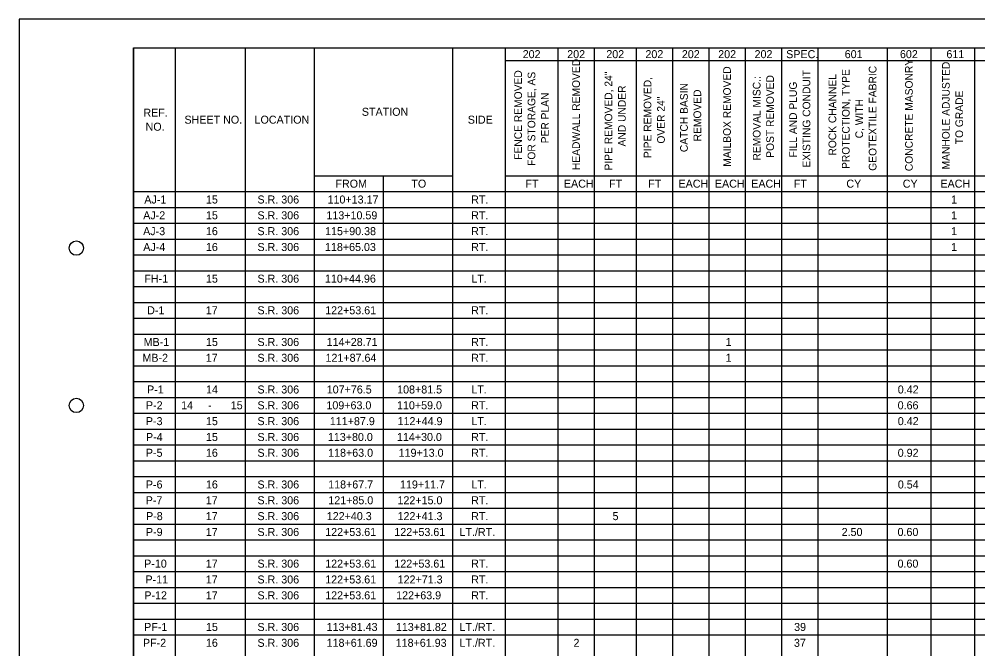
# Model space of a CAD drawing. Extents: x -16 to 102, y -13 to 9.
# Drawn here: x -16.37 to 0.4, y -1.91 to 9.09 of the extents above; entities that cross this region are included whole.
import ezdxf

# ---------------------------------------------------------------- set-up
doc = ezdxf.new("R2010")
doc.units = 0
for name, color, linetype in [('PV_P_EOP', 7, 'Continuous'), ('SH_Border', 7, 'Continuous'), ('SH_Cut_Line', 7, 'Continuous'), ('SH_Text', 7, 'Continuous'), ('TX_P_1', 7, 'Continuous')]:
    doc.layers.add(name, color=color, linetype=linetype)

msp = doc.modelspace()

# ---------------------------------------------------------------- linework, layer by layer
at = {"layer": 'SH_Border'}
msp.add_lwpolyline([(-14.371, 8.593), (17.129, 8.593), (17.129, -12.407), (-14.371, -12.407)], close=True, dxfattribs=at)
for centre in [(-15.371, 5.093), (-15.371, 2.343)]:
    msp.add_circle(centre, 0.125, dxfattribs=at)
at = {"layer": 'SH_Cut_Line'}
msp.add_lwpolyline([(-16.371, -12.907), (17.629, -12.907), (17.629, 9.093), (-16.371, 9.093)], close=True, dxfattribs=at)
at = {"layer": 'SH_Text'}
for p, q in [((-14.371, 8.593), (-12.42, 8.593)), ((-14.371, 8.593), (-14.371, -11.35)), ((-13.64, 8.593), (-13.64, -11.35)), ((-12.42, 8.593), (-10.002, 8.593)), ((-12.42, 8.593), (-12.42, -11.35)), ((-11.211, 8.593), (-11.211, -11.35)), ((-10.002, 8.593), (1.736, 8.593)), ((-8.793, 8.593), (-8.793, -11.35)), ((-7.871, 8.593), (-7.871, -11.881)), ((-6.948, 8.593), (-6.948, -11.881)), ((-6.312, 8.593), (-6.312, -11.881)), ((-5.58, 8.593), (-5.58, -11.881)), ((-4.944, 8.593), (-4.944, -11.881)), ((-4.308, 8.593), (-4.308, -11.881)), ((-3.672, 8.593), (-3.672, -11.881)), ((-3.035, 8.593), (-3.035, -11.881)), ((-2.399, 8.593), (-2.399, -11.881)), ((-1.19, 8.593), (-1.19, -11.881)), ((-0.427, 8.593), (-0.427, -11.881)), ((0.337, 8.593), (0.337, -11.881)), ((-7.871, 8.372), (1.736, 8.372)), ((-11.211, 6.357), (-10.002, 6.357)), ((-10.002, 6.357), (-8.793, 6.357)), ((-10.002, 6.357), (-10.002, -11.35)), ((-7.871, 6.357), (1.736, 6.357)), ((-14.371, 6.081), (-12.42, 6.081)), ((-12.42, 6.081), (-10.002, 6.081)), ((-10.002, 6.081), (1.736, 6.081)), ((-14.371, 5.804), (-12.42, 5.804)), ((-12.42, 5.804), (-10.002, 5.804)), ((-10.002, 5.804), (1.736, 5.804)), ((-14.371, 5.527), (-12.42, 5.527)), ((-12.42, 5.527), (-10.002, 5.527)), ((-10.002, 5.527), (1.736, 5.527)), ((-14.371, 5.251), (-12.42, 5.251)), ((-12.42, 5.251), (-10.002, 5.251)), ((-10.002, 5.251), (1.736, 5.251)), ((-14.371, 4.974), (-12.42, 4.974)), ((-12.42, 4.974), (-10.002, 4.974)), ((-10.002, 4.974), (1.736, 4.974)), ((-14.371, 4.697), (-12.42, 4.697)), ((-12.42, 4.697), (-10.002, 4.697)), ((-10.002, 4.697), (1.736, 4.697)), ((-14.371, 4.421), (-12.42, 4.421)), ((-12.42, 4.421), (-10.002, 4.421)), ((-10.002, 4.421), (1.736, 4.421)), ((-14.371, 4.144), (-12.42, 4.144)), ((-12.42, 4.144), (-10.002, 4.144)), ((-10.002, 4.144), (1.736, 4.144)), ((-14.371, 3.867), (-12.42, 3.867)), ((-12.42, 3.867), (-10.002, 3.867)), ((-10.002, 3.867), (1.736, 3.867)), ((-14.371, 3.591), (-12.42, 3.591)), ((-12.42, 3.591), (-10.002, 3.591)), ((-10.002, 3.591), (1.736, 3.591)), ((-14.371, 3.314), (-12.42, 3.314)), ((-12.42, 3.314), (-10.002, 3.314)), ((-10.002, 3.314), (1.736, 3.314)), ((-14.371, 3.037), (-12.42, 3.037)), ((-12.42, 3.037), (-10.002, 3.037)), ((-10.002, 3.037), (1.736, 3.037)), ((-14.371, 2.761), (-12.42, 2.761)), ((-12.42, 2.761), (-10.002, 2.761)), ((-10.002, 2.761), (1.736, 2.761)), ((-14.371, 2.484), (-12.42, 2.484)), ((-12.42, 2.484), (-10.002, 2.484)), ((-10.002, 2.484), (1.736, 2.484)), ((-14.371, 2.207), (-12.42, 2.207)), ((-12.42, 2.207), (-10.002, 2.207)), ((-10.002, 2.207), (1.736, 2.207)), ((-14.371, 1.931), (-12.42, 1.931)), ((-12.42, 1.931), (-10.002, 1.931)), ((-10.002, 1.931), (1.736, 1.931)), ((-14.371, 1.654), (-12.42, 1.654)), ((-12.42, 1.654), (-10.002, 1.654)), ((-10.002, 1.654), (1.736, 1.654)), ((-14.371, 1.377), (-12.42, 1.377)), ((-12.42, 1.377), (-10.002, 1.377)), ((-10.002, 1.377), (1.736, 1.377)), ((-14.371, 1.101), (-12.42, 1.101)), ((-12.42, 1.101), (-10.002, 1.101)), ((-10.002, 1.101), (1.736, 1.101)), ((-14.371, 0.824), (-12.42, 0.824)), ((-12.42, 0.824), (-10.002, 0.824)), ((-10.002, 0.824), (1.736, 0.824)), ((-14.371, 0.547), (-12.42, 0.547)), ((-12.42, 0.547), (-10.002, 0.547)), ((-10.002, 0.547), (1.736, 0.547)), ((-14.371, 0.271), (-12.42, 0.271)), ((-12.42, 0.271), (-10.002, 0.271)), ((-10.002, 0.271), (1.736, 0.271)), ((-14.371, -0.006), (-12.42, -0.006)), ((-12.42, -0.006), (-10.002, -0.006)), ((-10.002, -0.006), (1.736, -0.006)), ((-14.371, -0.283), (-12.42, -0.283)), ((-12.42, -0.283), (-10.002, -0.283)), ((-10.002, -0.283), (1.736, -0.283)), ((-14.371, -0.56), (-12.42, -0.56)), ((-12.42, -0.56), (-10.002, -0.56)), ((-10.002, -0.56), (1.736, -0.56)), ((-14.371, -0.836), (-12.42, -0.836)), ((-12.42, -0.836), (-10.002, -0.836)), ((-10.002, -0.836), (1.736, -0.836)), ((-14.371, -1.113), (-12.42, -1.113)), ((-12.42, -1.113), (-10.002, -1.113)), ((-10.002, -1.113), (1.736, -1.113)), ((-14.371, -1.39), (-12.42, -1.39)), ((-12.42, -1.39), (-10.002, -1.39)), ((-10.002, -1.39), (1.736, -1.39)), ((-14.371, -1.666), (-12.42, -1.666)), ((-12.42, -1.666), (-10.002, -1.666)), ((-10.002, -1.666), (1.736, -1.666))]:
    msp.add_line(p, q, dxfattribs=at)

# ---------------------------------------------------------------- texts
at = {"layer": 'PV_P_EOP'}
for s, p in [('STATION', (-10.377, 7.405)), ('REF.', (-14.198, 7.389)), ('SHEET NO.', (-13.48, 7.267)), ('LOCATION', (-12.254, 7.267)), ('SIDE', (-8.524, 7.267)), ('NO.', (-14.16, 7.144)), ('FROM', (-10.839, 6.149)), ('TO', (-9.511, 6.149))]:
    msp.add_text(s, height=0.14, dxfattribs=at).set_placement(p)
at = {"layer": 'TX_P_1'}
for s, p in [('202', (-7.564, 8.412)), ('202', (-6.785, 8.412)), ('202', (-6.101, 8.412)), ('202', (-5.417, 8.412)), ('202', (-4.78, 8.412)), ('202', (-4.144, 8.412)), ('202', (-3.508, 8.412)), ('SPEC.', (-2.955, 8.412)), ('601', (-1.931, 8.412)), ('602', (-0.965, 8.412)), ('611', (-0.152, 8.412)), ('FT', (-7.515, 6.149)), ('EACH', (-6.843, 6.149)), ('FT', (-6.052, 6.149)), ('FT', (-5.368, 6.149)), ('EACH', (-4.838, 6.149)), ('EACH', (-4.202, 6.149)), ('EACH', (-3.566, 6.149)), ('FT', (-2.823, 6.149)), ('CY', (-1.902, 6.149)), ('CY', (-0.916, 6.149)), ('EACH', (-0.257, 6.149)), ('AJ-1', (-14.182, 5.872)), ('15', (-13.104, 5.872)), ('S.R. 306', (-12.203, 5.872)), ('110+13.17', (-10.977, 5.872)), ('RT.', (-8.465, 5.872)), ('1', (-0.07, 5.872)), ('AJ-2', (-14.202, 5.596)), ('15', (-13.104, 5.596)), ('S.R. 306', (-12.203, 5.596)), ('113+10.59', (-10.997, 5.596)), ('RT.', (-8.465, 5.596)), ('1', (-0.07, 5.596)), ('AJ-3', (-14.203, 5.319)), ('16', (-13.105, 5.319)), ('S.R. 306', (-12.203, 5.319)), ('115+90.38', (-11.02, 5.319)), ('RT.', (-8.465, 5.319)), ('1', (-0.07, 5.319)), ('AJ-4', (-14.201, 5.042)), ('16', (-13.105, 5.042)), ('S.R. 306', (-12.203, 5.042)), ('118+65.03', (-11.022, 5.042)), ('RT.', (-8.465, 5.042)), ('1', (-0.07, 5.042)), ('FH-1', (-14.181, 4.489)), ('15', (-13.104, 4.489)), ('S.R. 306', (-12.203, 4.489)), ('110+44.96', (-11.023, 4.489)), ('LT.', (-8.462, 4.489)), ('D-1', (-14.133, 3.936)), ('17', (-13.107, 3.936)), ('S.R. 306', (-12.203, 3.936)), ('122+53.61', (-11.018, 3.936)), ('RT.', (-8.465, 3.936)), ('MB-1', (-14.194, 3.382)), ('15', (-13.104, 3.382)), ('S.R. 306', (-12.203, 3.382)), ('114+28.71', (-10.993, 3.382)), ('RT.', (-8.465, 3.382)), ('1', (-4.015, 3.382)), ('MB-2', (-14.215, 3.106)), ('17', (-13.107, 3.106)), ('S.R. 306', (-12.203, 3.106)), ('121+87.64', (-11.013, 3.106)), ('RT.', (-8.465, 3.106)), ('1', (-4.015, 3.106)), ('P-1', (-14.134, 2.552)), ('14', (-13.103, 2.552)), ('S.R. 306', (-12.203, 2.552)), ('107+76.5', (-10.991, 2.552)), ('108+81.5', (-9.76, 2.552)), ('LT.', (-8.462, 2.552)), ('0.42', (-1.003, 2.552)), ('P-2', (-14.154, 2.276)), ('14', (-13.538, 2.276)), ('15', (-12.67, 2.276)), ('S.R. 306', (-12.203, 2.276)), ('109+63.0', (-10.997, 2.276)), ('110+59.0', (-9.762, 2.276)), ('RT.', (-8.465, 2.276)), ('0.66', (-1.005, 2.276)), ('-', (-13.067, 2.276)), ('P-3', (-14.155, 1.999)), ('15', (-13.104, 1.999)), ('S.R. 306', (-12.203, 1.999)), ('111+87.9', (-10.937, 1.999)), ('112+44.9', (-9.753, 1.999)), ('LT.', (-8.462, 1.999)), ('0.42', (-1.003, 1.999)), ('P-4', (-14.153, 1.722)), ('15', (-13.104, 1.722)), ('S.R. 306', (-12.203, 1.722)), ('113+80.0', (-10.971, 1.722)), ('114+30.0', (-9.763, 1.722)), ('RT.', (-8.465, 1.722)), ('P-5', (-14.155, 1.446)), ('16', (-13.105, 1.446)), ('S.R. 306', (-12.203, 1.446)), ('118+63.0', (-10.967, 1.446)), ('119+13.0', (-9.734, 1.446)), ('RT.', (-8.465, 1.446)), ('0.92', (-1.004, 1.446)), ('P-6', (-14.155, 0.892)), ('16', (-13.105, 0.892)), ('S.R. 306', (-12.203, 0.892)), ('118+67.7', (-10.966, 0.892)), ('119+11.7', (-9.71, 0.892)), ('LT.', (-8.462, 0.892)), ('0.54', (-1.002, 0.892)), ('P-7', (-14.158, 0.616)), ('17', (-13.107, 0.616)), ('S.R. 306', (-12.203, 0.616)), ('121+85.0', (-10.964, 0.616)), ('122+15.0', (-9.754, 0.616)), ('RT.', (-8.465, 0.616)), ('P-8', (-14.152, 0.339)), ('17', (-13.107, 0.339)), ('S.R. 306', (-12.203, 0.339)), ('122+40.3', (-10.991, 0.339)), ('122+41.3', (-9.753, 0.339)), ('RT.', (-8.465, 0.339)), ('5', (-5.992, 0.339)), ('P-9', (-14.154, 0.062)), ('17', (-13.107, 0.062)), ('S.R. 306', (-12.203, 0.062)), ('122+53.61', (-11.018, 0.062)), ('122+53.61', (-9.809, 0.062)), ('LT./RT.', (-8.669, 0.062)), ('2.50', (-1.985, 0.062)), ('0.60', (-1.007, 0.062)), ('P-10', (-14.185, -0.491)), ('17', (-13.107, -0.491)), ('S.R. 306', (-12.203, -0.491)), ('122+53.61', (-11.018, -0.491)), ('122+53.61', (-9.809, -0.491)), ('RT.', (-8.465, -0.491)), ('0.60', (-1.007, -0.491)), ('P-11', (-14.162, -0.768)), ('17', (-13.107, -0.768)), ('S.R. 306', (-12.203, -0.768)), ('122+53.61', (-11.018, -0.768)), ('122+71.3', (-9.751, -0.768)), ('RT.', (-8.465, -0.768)), ('P-12', (-14.182, -1.045)), ('17', (-13.107, -1.045)), ('S.R. 306', (-12.203, -1.045)), ('122+53.61', (-11.018, -1.045)), ('122+63.9', (-9.777, -1.045)), ('RT.', (-8.465, -1.045)), ('PF-1', (-14.185, -1.598)), ('15', (-13.104, -1.598)), ('S.R. 306', (-12.203, -1.598)), ('113+81.43', (-10.993, -1.598)), ('113+81.82', (-9.782, -1.598)), ('LT./RT.', (-8.669, -1.598)), ('39', (-2.816, -1.598)), ('PF-2', (-14.206, -1.875)), ('16', (-13.105, -1.875)), ('S.R. 306', (-12.203, -1.875)), ('118+61.69', (-10.993, -1.875)), ('118+61.93', (-9.785, -1.875)), ('LT./RT.', (-8.669, -1.875)), ('2', (-6.675, -1.875)), ('37', (-2.819, -1.875))]:
    msp.add_text(s, height=0.14, dxfattribs=at).set_placement(p)
for s, height, p in [('HEADWALL REMOVED', 0.13414, (-6.563, 6.456)), ('CONCRETE MASONRY', 0.13414, (-0.741, 6.437)), ('MAILBOX REMOVED', 0.13414, (-3.923, 6.515)), ('GEOTEXTILE FABRIC', 0.13414, (-1.376, 6.444)), ('MANHOLE ADJUSTED', 0.13414, (-0.095, 6.467)), ('FENCE REMOVED', 0.13414, (-7.577, 6.636)), ('FOR STORAGE, AS', 0.13414, (-7.343, 6.529)), ('PIPE REMOVED, 24"', 0.13414, (-5.997, 6.449)), ('PIPE REMOVED,', 0.13414, (-5.313, 6.667)), ('REMOVAL MISC.:', 0.13414, (-3.404, 6.622)), ('POST REMOVED', 0.13414, (-3.169, 6.671)), ('EXISTING CONDUIT', 0.13414, (-2.533, 6.5)), ('ROCK CHANNEL', 0.13414, (-2.08, 6.709)), ('PROTECTION, TYPE', 0.13414, (-1.845, 6.476)), ('AND UNDER', 0.1341, (-5.762, 6.869)), ('CATCH BASIN', 0.13414, (-4.676, 6.77)), ('FILL AND PLUG', 0.13414, (-2.768, 6.676)), ('PER PLAN', 0.1341, (-7.108, 6.924)), ('OVER 24"', 0.1341, (-5.078, 6.919)), ('REMOVED', 0.1341, (-4.442, 6.958)), ('TO GRADE', 0.1341, (0.139, 6.908)), ('C, WITH', 0.1341, (-1.61, 7.011))]:
    msp.add_text(s, height=height, rotation=90, dxfattribs=at).set_placement(p)

doc.saveas('drawing.dxf')
